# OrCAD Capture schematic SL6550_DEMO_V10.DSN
size Custom; title: SL6550_DEMO_V1.0; rev: V01; note: 4
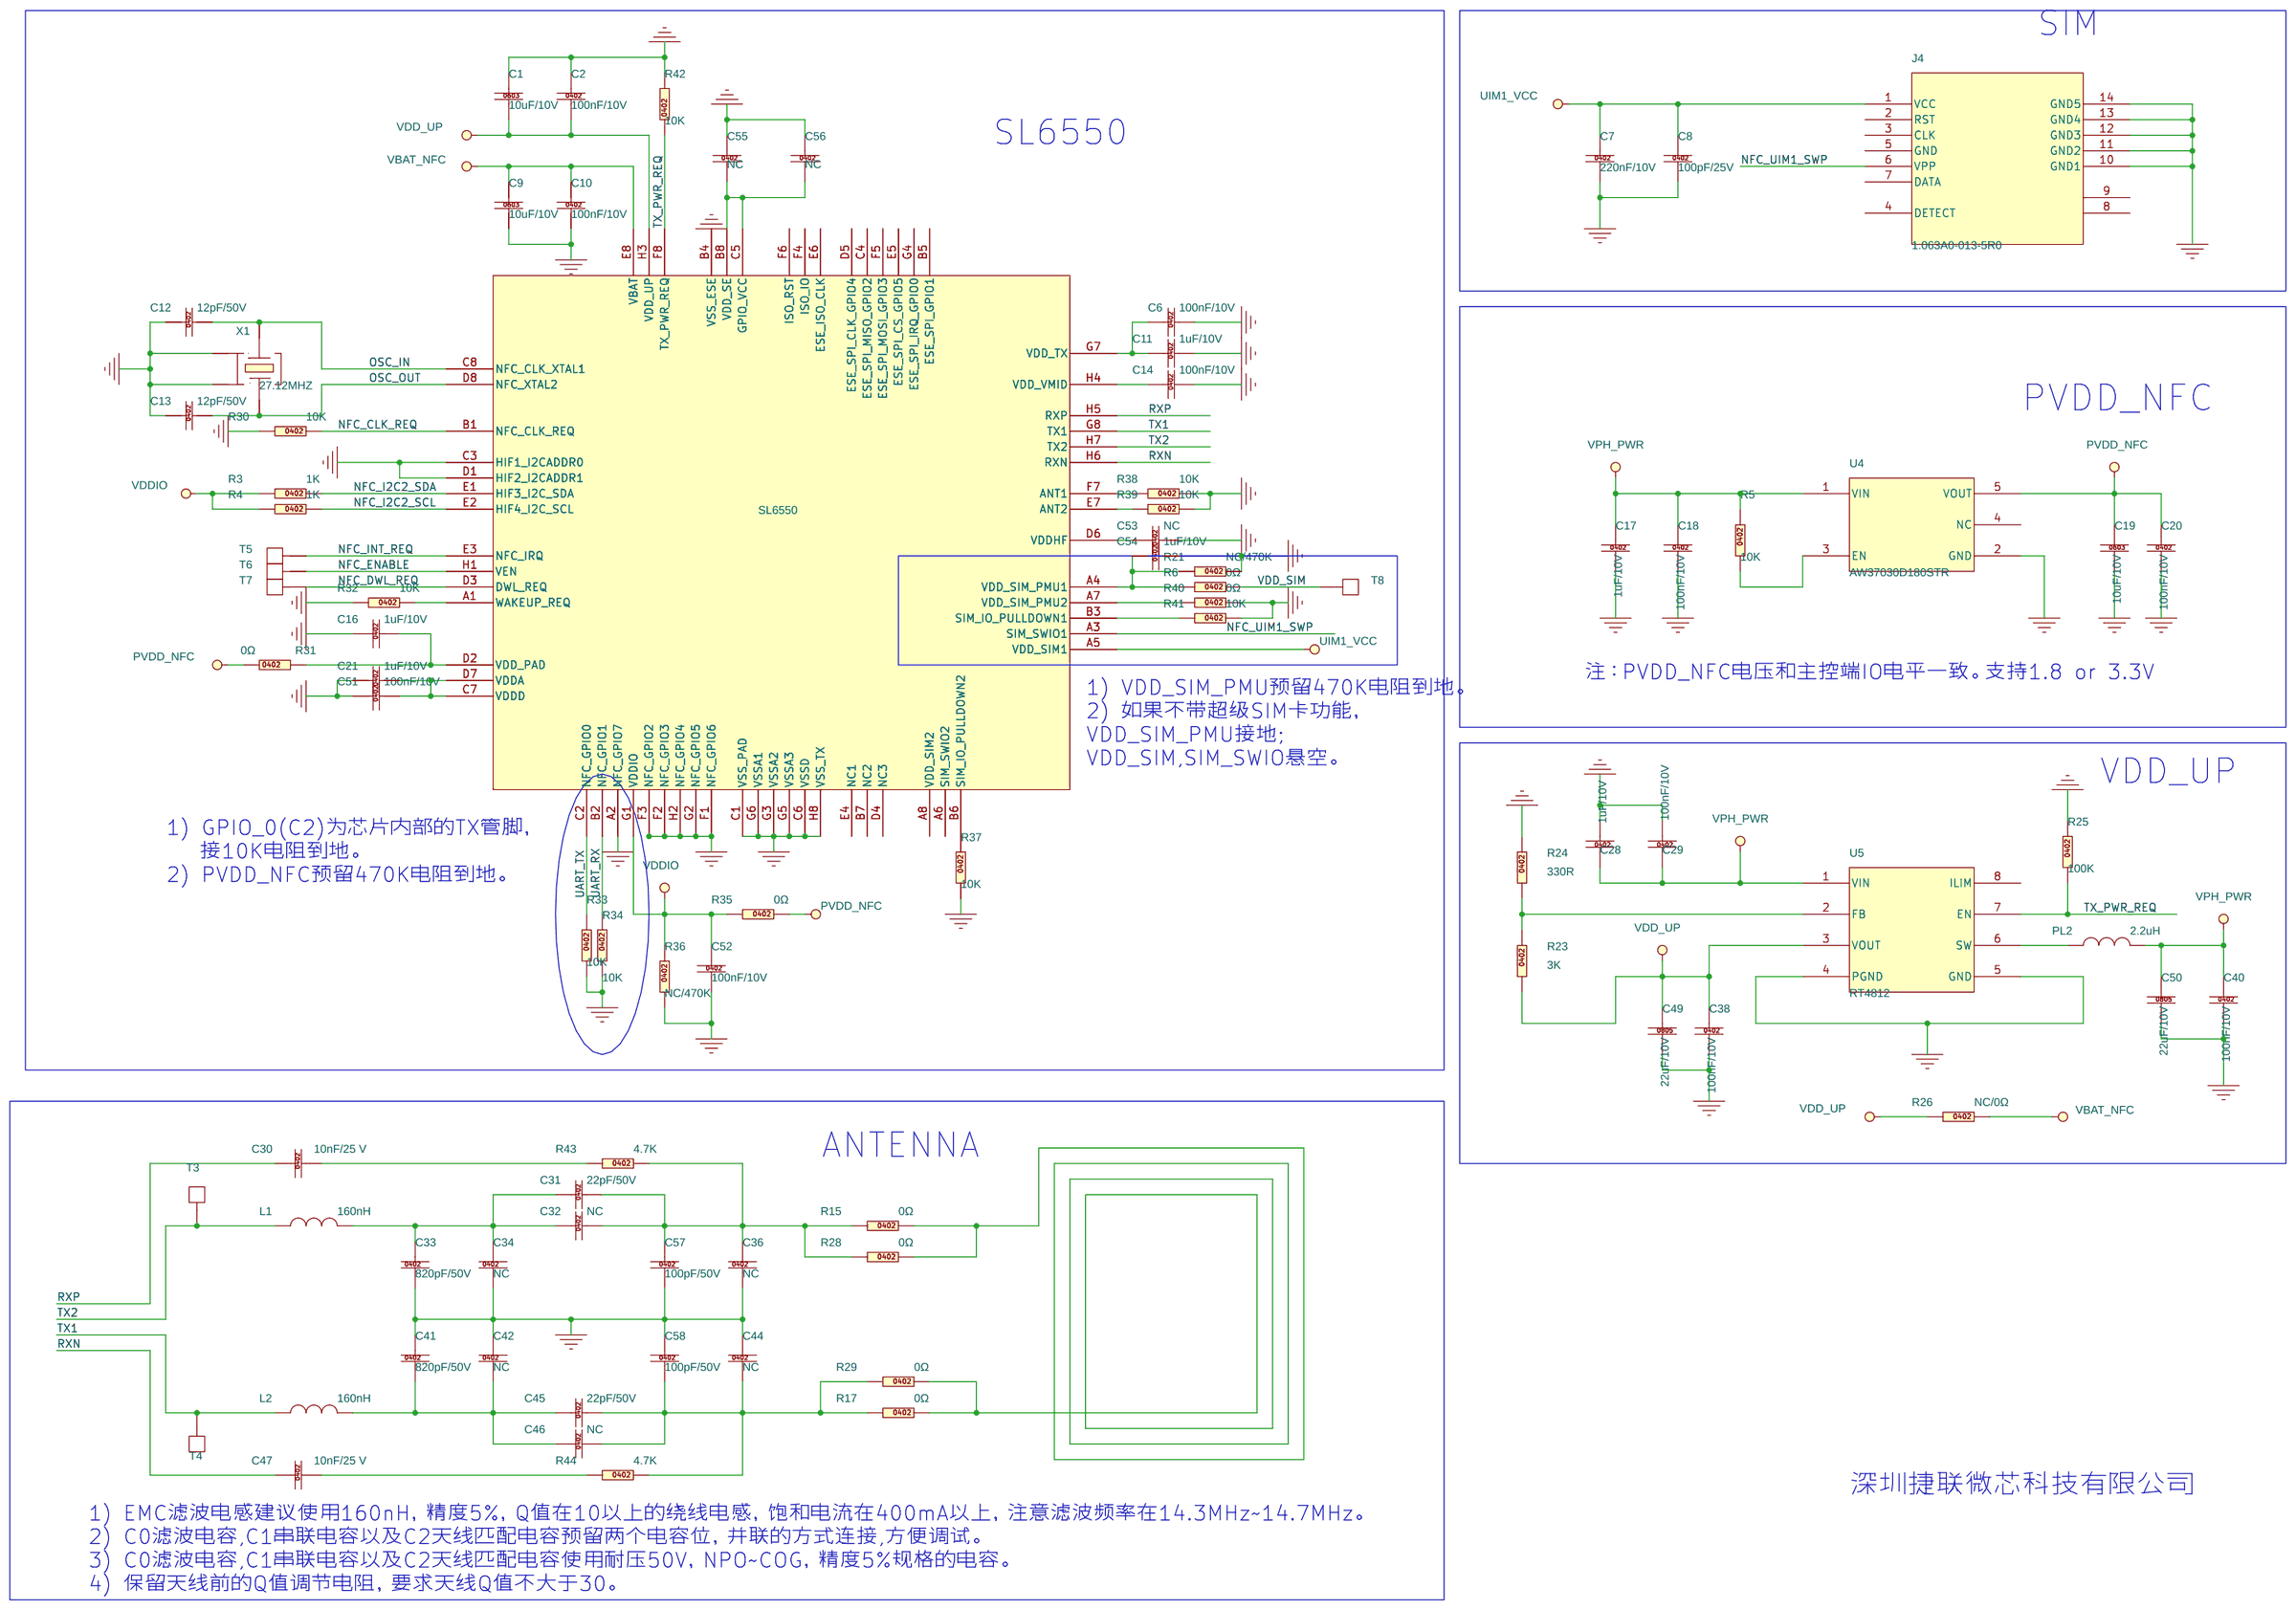
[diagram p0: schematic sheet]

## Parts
C1  10uF/10V  [C0603-10]
C2  100nF/10V  [C0402-04]
C6  100nF/10V  [C0402-04]
C7  220nF/10V  [C0402-05]
C8  100pF/25V  [C0402-06]
C9  10uF/10V  [C0603-10]
C10  100nF/10V  [C0402-04]
C11  1uF/10V  [C0402-06]
C12  12pF/50V  [C0402-06]
C13  12pF/50V  [C0402-06]
C14  100nF/10V  [C0402-04]
C16  1uF/10V  [C0402-06]
C17  1uF/10V  [C0402-06]
C18  100nF/10V  [C0402-04]
C19  10uF/10V  [C0603-10]
C20  100nF/10V  [C0402-04]
C21  1uF/10V  [C0402-06]
C28  1uF/10V  [C0402-06]
C29  100nF/10V  [C0402-04]
C30  10nF/25 V  [C0402-05]
C31  22pF/50V  [C0402-06]
C32  NC  [C0402-06]
C33  820pF/50V  [C0402-06]
C34  NC  [C0402-06]
C36  NC  [C0402-06]
C38  100nF/10V  [C0402-04]
C40  100nF/10V  [C0402-04]
C41  820pF/50V  [C0402-06]
C42  NC  [C0402-06]
C44  NC  [C0402-06]
C45  22pF/50V  [C0402-06]
C46  NC  [C0402-06]
C47  10nF/25 V  [C0402-05]
C49  22uF/10V  [C0805-09]
C50  22uF/10V  [C0805-09]
C51  100nF/10V  [C0402-04]
C52  100nF/10V  [C0402-04]
C53  NC  [C0402-04]
C54  1uF/10V  [C0402-06]
C55  NC  [C0402-04]
C56  NC  [C0402-06]
C57  100pF/50V  [C0402-06]
C58  100pF/50V  [C0402-06]
J4  1.063A0-013-5R0  [MC02-61150-7R_SIM1]
L1  160nH  [C0603-10]
L2  160nH  [C0603-10]
PL2  2.2uH  [PL4040-18]
R3  1K  [R0402-04]
R4  1K  [R0402-04]
R5  10K  [R0402-04]
R6  0Ω  [R0402-04]
R15  0Ω  [R0402-04]
R17  0Ω  [R0402-04]
R21  NC/470K  [R0402-04]
R23  3K  [R0402-04]
R24  330R  [R0402-04]
R25  100K  [R0402-04]
R26  NC/0Ω  [R0402-04]
R28  0Ω  [R0402-04]
R29  0Ω  [R0402-04]
R30  10K  [R0402-04]
R31  0Ω  [R0402-04]
R32  10K  [R0402-04]
R33  10K  [R0402-04]
R34  10K  [R0402-04]
R35  0Ω  [R0402-04]
R36  NC/470K  [R0402-04]
R37  10K  [R0402-04]
R38  10K  [R0402-04]
R39  10K  [R0402-04]
R40  0Ω  [R0402-04]
R41  10K  [R0402-04]
R42  10K  [R0402-04]
R43  4.7K  [R0402-04]
R44  4.7K  [R0402-04]
T3  0.24mm  [TP1_0]
T4  0.24mm  [TP1_0]
T5  0.24mm  [TP1_0]
T6  0.24mm  [TP1_0]
T7  0.24mm  [TP1_0]
T8  0.24mm  [TP1_0]
U4  AW37030D180STR  [SOT23-5-12]
U5  RT4812  [TSOT-23-8]
U6  SL6550  [BGA-64-0.4PITCH]
X1  27.12MHZ  [X4-3225-09]

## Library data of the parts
C1 C9 C19 = 31002000154: PART_NAME: 陶瓷电容
C2 C6 C10 C14 C18 C20 C29 C38 C40 C51-C53 C55 = 31002000872: PART_NAME: 陶瓷电容
C7 = 31002000797
C8 = 31002000490
C11 C16 C17 C21 C28 C54 C56 = 31002000574: PART_NAME: 陶瓷电容
C12 C13 = 31002000217
C30 C47 = C0402: 陶瓷电容/10nF/±10%/25V/X7R/0402/0.55mm/-55~125℃; Manufacturer: MURATA; Part Name: 陶瓷电容; Part Number: GRM155R71E103KA01D; Part_Number: 31002000285
C31-C34 C36 C41 C42 C44-C46 = 31002000729: PART_NAME: 陶瓷电容
C49 C50 = 31002000766
C57 C58 = 31002000249
J4 = 1_2.063A0-013-5R0
L1 = MWSD1608F
L2 = MWSD1608F_1
PL2 = 31008000121: PART_NAME: 功率电感
R3 R4 = 31003001157: PART_NAME: 贴片电阻
R5 R30 R32-R34 R37-R39 R41 R42 = 31003000947: PART_NAME: 贴片电阻
R6 R15 R17 R26 R28 R29 R31 R35 R40 = 31003001357: PART_NAME: 贴片电阻
R21 R36 = 31003001082
R23 = 31003000334
R24 = 31003000950
R25 = 31003000948
R43 R44 = 31003000354
T3-T8 = TP_0.24mm
U4 = AW37030D180STR
U5 = RT4812_0
U6 = SL6550_0
X1 = XTAL_4P: 无源晶振/8 MHz/20 ppm/30 ppm/12 pF/500 Ω/3 pF/0.0002 W/3.2 mm*2.5 mm*0.75 mm/-40~85℃℃; Manufacturer: 鸿星/HOSONIC; Part Name: 无源晶振; Part Number: E3SB8E0009202E; Part_Number: 31053000072

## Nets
GND: C1.1 C2.1 C6.2 C7.2 C8.2 C9.2 C10.2 C11.2 C12.1 C13.1 C14.2 C16.1 C17.2 C18.2 C19.2 C20.2 C21.1 C28.2 C29.2 C33.2 C34.2 C36.2 C38.2 C40.2 C41.1 C42.1 C44.1 C49.2 C50.2 C51.1 C52.2 C53.2 C54.2 C55.1 C56.1 C57.2 C58.1 J4.10(GND1) J4.11(GND2) J4.12(GND3) J4.13(GND4) J4.14(GND5) R21.2 R24.2 R25.2 R30.1 R32.1 R33.1 R34.1 R36.1 R37.1 R38.2 R39.2 R40.2 R41.2 R42.1 U4.2(GND) U5.4(PGND) U5.5(GND) U6.A2(NFC_GPIO7) U6.B4(VSS_ESE) U6.C1(VSS_PAD) U6.C3(HIF1_I2CADDR0) U6.C6(VSSD) U6.D1(HIF2_I2CADDR1) U6.F1(NFC_GPIO6) U6.F2(NFC_GPIO3) U6.F3(NFC_GPIO2) U6.G2(NFC_GPIO5) U6.G3(VSSA2) U6.G5(VSSA3) U6.G6(VSSA1) U6.H2(NFC_GPIO4) U6.H8(VSS_TX) X1.2 X1.4
PVDD_NFC: C19.1 C20.1 R31.2 R35.2 U4.5(VOUT)
VBAT_NFC: C9.1 C10.1 R26.2 U6.E8(VBAT)
VDD_SIM: R6.2 T8.1
VDD_UP: C1.2 C2.2 C38.1 C49.1 R23.1 R26.1 U5.3(VOUT) U6.H3(VDD_UP)
VDDIO: C52.1 R3.1 R4.1 R35.1 R36.2 U6.G1(VDDIO)
NFC_CLK_REQ: R30.2 U6.B1(NFC_CLK_REQ)
NFC_DWL_REQ: T7.1 U6.D3(DWL_REQ)
NFC_ENABLE: T6.1 U6.H1(VEN)
NFC_I2C2_SCL: R4.2 U6.E2(HIF4_I2C_SCL)
NFC_I2C2_SDA: R3.2 U6.E1(HIF3_I2C_SDA)
NFC_INT_REQ: T5.1 U6.E3(NFC_IRQ)
NFC_UIM1_SWP: J4.6(VPP) U6.A3(SIM_SWIO1)
OSC_IN: C12.2 U6.C8(NFC_CLK_XTAL1) X1.1
OSC_OUT: C13.2 U6.D8(NFC_XTAL2) X1.3
RXN: C47.1 U6.H6(RXN)
RXP: C30.1 U6.H5(RXP)
TX1: L2.1 T4.1 U6.G8(TX1)
TX2: L1.1 T3.1 U6.H7(TX2)
TX_PWR_REQ: R25.1 R42.2 U5.7(EN) U6.F8(TX_PWR_REQ)
UART_RX: R34.2 U6.B2(NFC_GPIO1)
UART_TX: R33.2 U6.C2(NFC_GPIO0)
UIM1_VCC: C7.1 C8.1 J4.1(VCC) U6.A5(VDD_SIM1)
VPH_PWR: C17.1 C18.1 C28.1 C29.1 C40.1 C50.1 PL2.2 R5.2 U4.1(VIN) U5.1(VIN)
N04213: C14.1 U6.H4(VDD_VMID)
N04447: C54.1 R6.1 R21.1 U6.A4(VDD_SIM_PMU1)
N04709: R15.2 R17.2 R28.2 R29.2
N04773: C30.2 R43.1
N04777: C31.2 C32.2 C36.1 C57.1 R15.1 R28.1 R43.2
N04835: C31.1 C32.1 C33.1 C34.1 L1.2
N05113: C44.2 C45.2 C46.2 C58.2 R17.1 R29.1 R44.2
N05225: C41.2 C42.2 C45.1 C46.1 L2.2
N05373: C47.2 R44.1
N07233: R5.1 U4.3(EN)
N14823: R23.2 R24.1 U5.2(FB)
N15868: PL2.1 U5.6(SW)
N69685: R38.1 U6.F7(ANT1)
N69723: R39.1 U6.E7(ANT2)
N70190: C6.1 C11.1 U6.G7(VDD_TX)
N72162: C53.1 U6.D6(VDDHF)
N74598: R40.1 U6.A7(VDD_SIM_PMU2)
N74630: R41.1 U6.B3(SIM_IO_PULLDOWN1)
N79745: C55.2 C56.2 U6.B8(VDD_SE) U6.C5(GPIO_VCC)
N84502: R32.2 U6.A1(WAKEUP_REQ)
N84530: C16.2 R31.1 U6.D2(VDD_PAD)
N84618: C21.2 C51.2 U6.C7(VDDD) U6.D7(VDDA)
N107577: R37.2 U6.B6(SIM_IO_PULLDOWN2)

Not connected (* = marked no-connect by the designer): J4 2(RST) 3(CLK) 4(DETECT) 5(GND) 7(DATA) 8 9; U4 4(NC); U5 8(ILIM); U6 A6(SIM_SWIO2) A8(VDD_SIM2) B5(ESE_SPI_GPIO1) B7(NC2) C4(ESE_SPI_MISO_GPIO2) D4(NC3) D5(ESE_SPI_CLK_GPIO4) E4(NC1) E5(ESE_SPI_CS_GPIO5) E6(ESE_ISO_CLK) F4(ISO_IO) F5(ESE_SPI_MOSI_GPIO3) F6(ISO_RST) G4(ESE_SPI_IRQ_GPIO0)

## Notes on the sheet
- SIM
- SL6550
- PVDD_NFC
- 1) VDD_SIM_PMU预留470K电阻到地。
  2) 如果不带超级SIM卡功能，
  VDD_SIM_PMU接地;
  VDD_SIM,SIM_SWIO悬空。
- 注：PVDD_NFC电压和主控端IO电平一致。支持1.8 or 3.3V
- VDD_UP
- 1) GPIO_0(C2)为芯片内部的TX管脚，
     接10K电阻到地。
  2) PVDD_NFC预留470K电阻到地。
- ANTENNA
- 深圳捷联微芯科技有限公司
- 1) EMC滤波电感建议使用160nH，精度5%，Q值在10以上的绕线电感，饱和电流在400mA以上，注意滤波频率在14.3MHz~14.7MHz。
  2) C0滤波电容,C1串联电容以及C2天线匹配电容预留两个电容位，并联的方式连接,方便调试。
  3) C0滤波电容,C1串联电容以及C2天线匹配电容使用耐压50V，NPO~COG，精度5%规格的电容。
  4) 保留天线前的Q值调节电阻，要求天线Q值不大于30。
